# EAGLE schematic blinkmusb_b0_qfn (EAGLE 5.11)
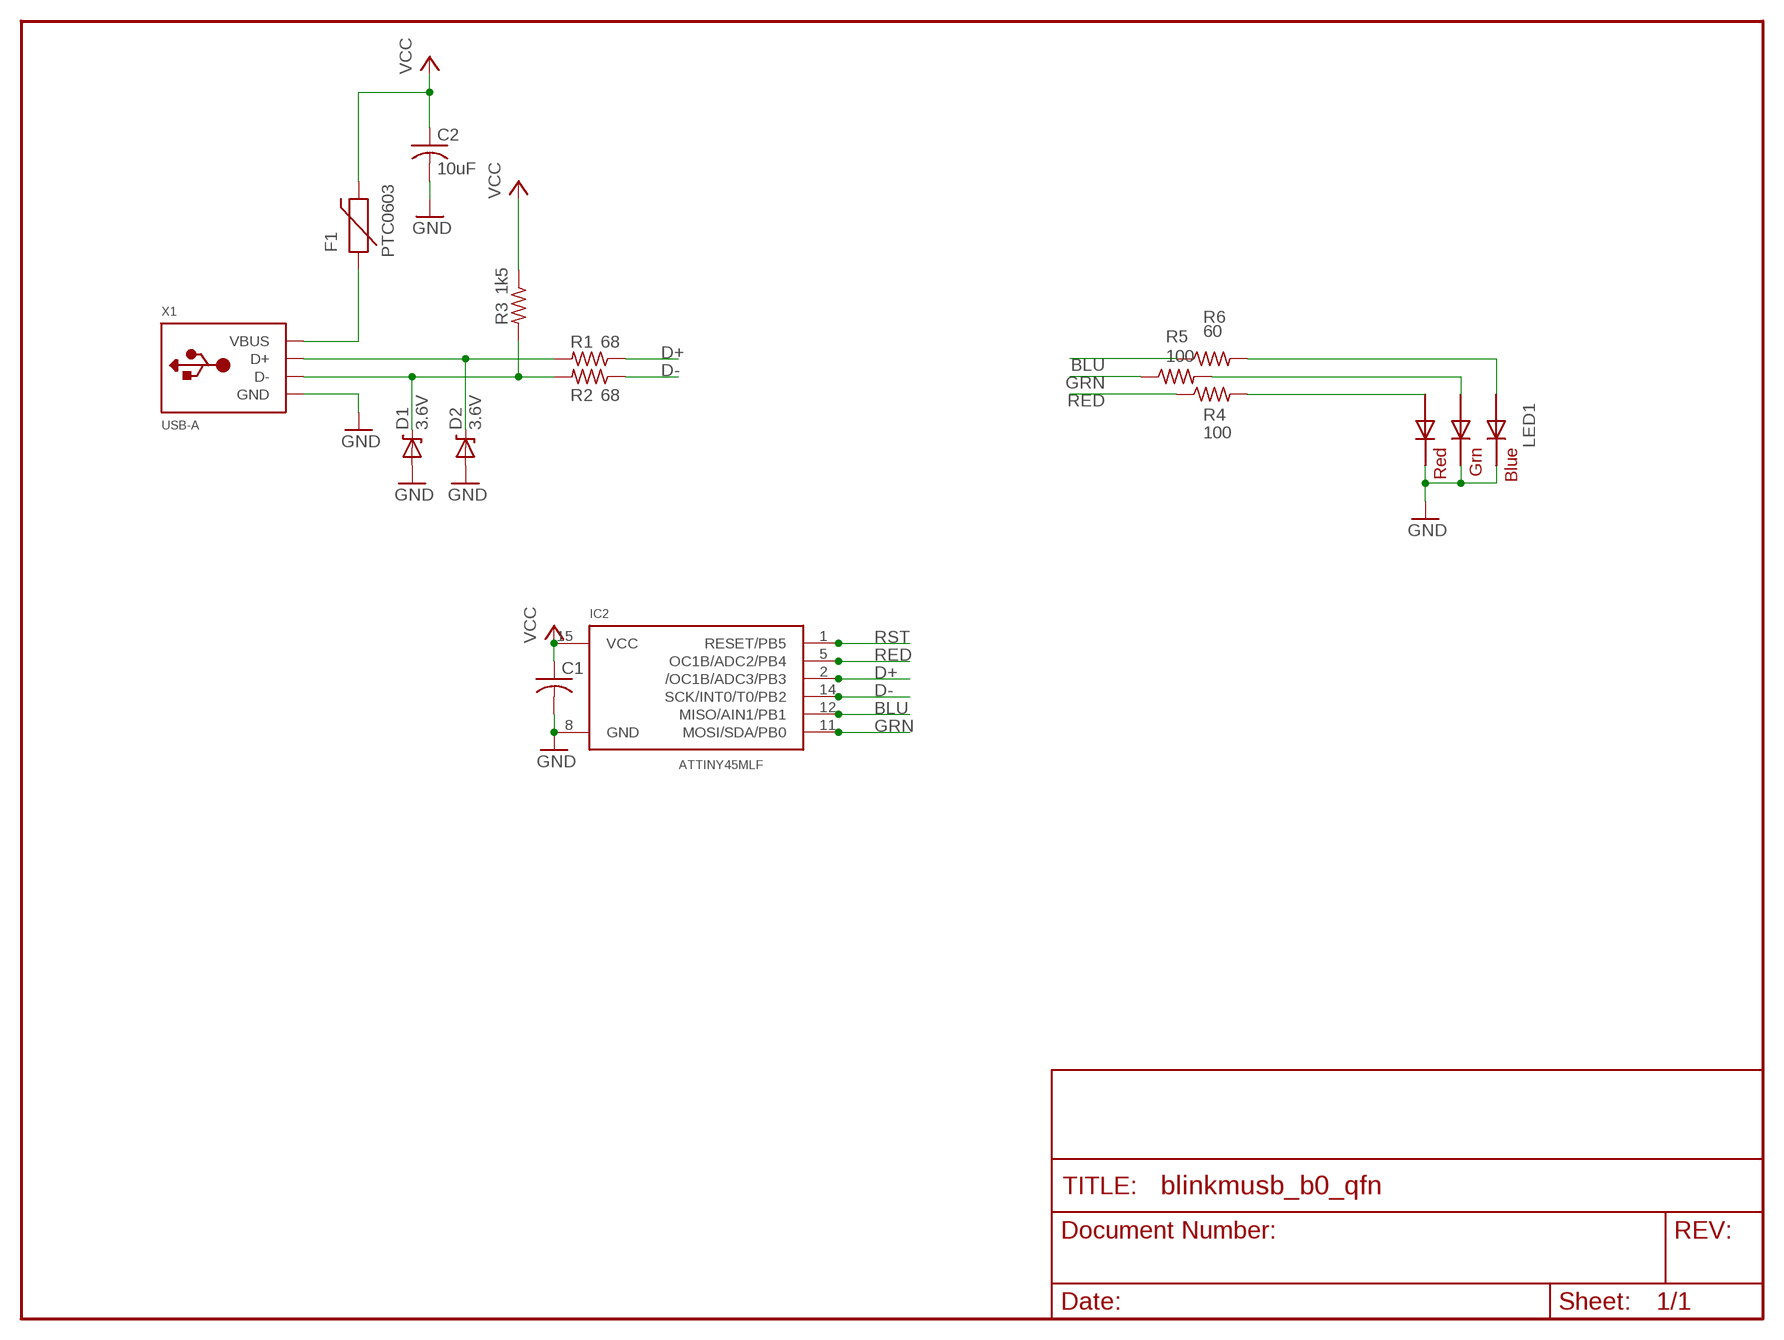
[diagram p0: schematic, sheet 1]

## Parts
C1  C-USC0603  [C0603]
C2  10uF  C-USC0603  [C0603]
D1  3.6V  DIODE-ZENER-BZT52  [SOD-323]
D2  3.6V  DIODE-ZENER-BZT52  [SOD-323]
F1  PTC0603  [0603]
IC2  ATTINY45MLF  [MLF20]
LED1  RGBLED5050  [RGBLED5050]
R1  68  R-US_R0603  [R0603]
R2  68  R-US_R0603  [R0603]
R3  1k5  R-US_R0603  [R0603]
R4  100  R-US_R0603  [R0603]
R5  100  R-US_R0603  [R0603]
R6  60  R-US_R0603  [R0603]
X1  USB-A  [MOLEX_480371000]

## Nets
BLU: IC2.12(MISO/AIN1/PB1) R6.1
D+: IC2.2(/OC1B/ADC3/PB3) R1.1
D-: IC2.14(SCK/INT0/T0/PB2) R2.1
GND: C1.2 C2.2 D1.2(A) D2.2(A) IC2.8(GND) LED1.4(BLUE_C) LED1.5(RED_C) LED1.6(GREEN_C) X1.4(GND)
GRN: IC2.11(MOSI/SDA/PB0) R5.1
N$4: D2.1(C) R1.2 X1.3(D+)
N$5: D1.1(C) R2.2 R3.2 X1.2(D-)
N$13: F1.1 X1.1(VBUS)
RBLU: LED1.3(BLUE_A) R6.2
RED: IC2.5(OC1B/ADC2/PB4) R4.1
RGRN: LED1.1(GREEN_A) R5.2
RRED: LED1.2(RED_A) R4.2
RST: IC2.1(RESET/PB5)
VCC: C1.1 C2.1 F1.2 IC2.15(VCC) R3.1

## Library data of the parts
C1 C2 = rcl:C-US: CAPACITOR, American symbol
D1 D2 = SparkFun-20110517:DIODE-ZENER: Zener Diode
F1 = SparkFun-20110517:PTC: Resettable Fuse PTC
IC2 = todstuff:ATTINY45
LED1 = adafruit-20120122:RGBLED: For 5050 RGB LEDs, the order of the LEDs may vary from one manufacturer to another!
R1-R6 = rcl:R-US_: RESISTOR, American symbol
X1 = adafruit-20120122:USB-A: USB type A 'plug' Used for things that can directly connect to a USB port, say USB key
